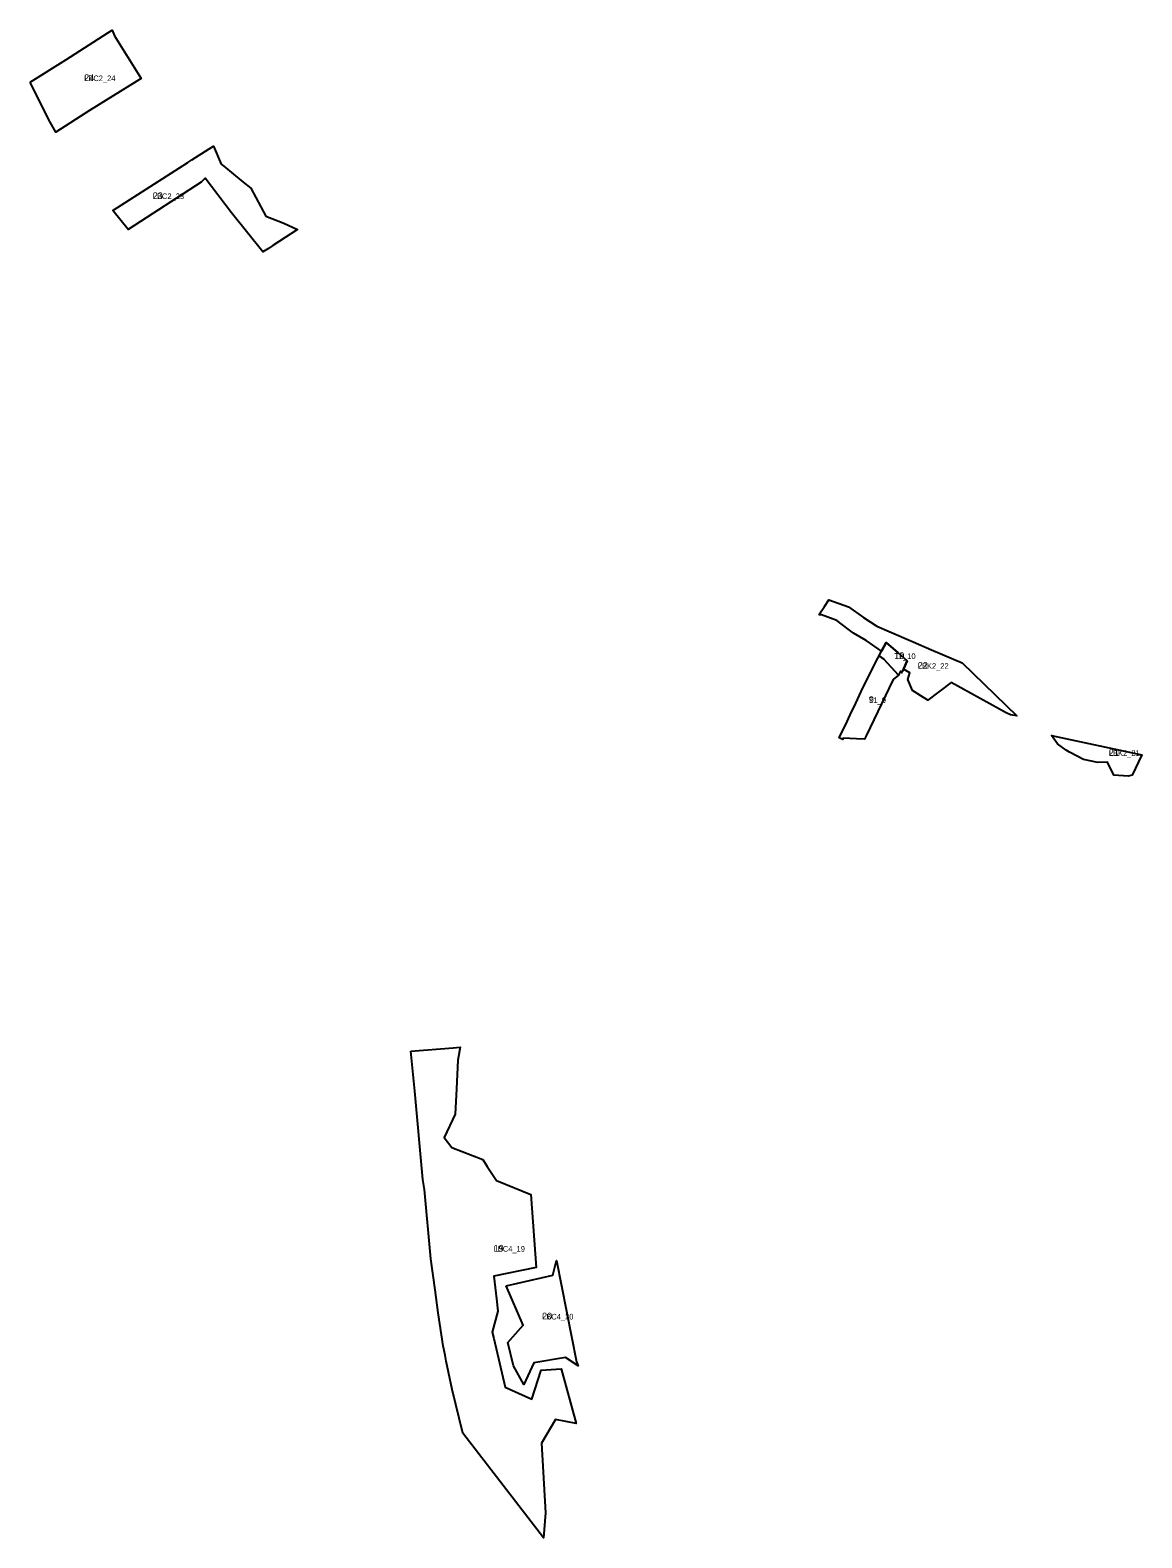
# Model space of a CAD drawing. Extents: x -521969 to -519935, y -1141664 to -1140238.
import ezdxf

# ---------------------------------------------------------------- set-up
doc = ezdxf.new("R2010")
doc.units = 0
for name, color, linetype in [('96120023', 7, 'Continuous'), ('96140023', 7, 'Continuous'), ('ID_VPO', 7, 'Continuous'), ('ID_VPS', 7, 'Continuous')]:
    doc.layers.add(name, color=color, linetype=linetype)

msp = doc.modelspace()

# ---------------------------------------------------------------- linework, layer by layer
at = {"layer": '96120023'}
for points in [[(-520162.5, -1140867.2), (-520152.1, -1140876.1), (-520143.8, -1140883.3), (-520147.2, -1140890.7), (-520148.3, -1140893), (-520148.7, -1140894), (-520149.9, -1140892.7), (-520151.7, -1140896.3), (-520164.6, -1140882), (-520168.9, -1140879), (-520167.8, -1140876.9), (-520166.6, -1140874.8)], [(-520164.6, -1140882), (-520151.7, -1140896.3), (-520156.2, -1140899.9), (-520180.3, -1140950.1), (-520181.8, -1140953.2), (-520189, -1140952.9), (-520200.8, -1140952.2), (-520201.3, -1140953.3), (-520201.3, -1140953.3), (-520204.3, -1140952), (-520197.4, -1140937.4), (-520196.1, -1140934.7), (-520193, -1140928.2), (-520191.2, -1140924.3), (-520184.7, -1140910.7), (-520178.7, -1140898.1), (-520170.1, -1140881.1), (-520168.9, -1140879)]]:
    msp.add_lwpolyline(points, close=True, dxfattribs=at)
at = {"layer": '96140023'}
for points in [[(-520925, -1140368.1), (-520893.1, -1140348.3), (-520855.9, -1140324.2), (-520852.1, -1140321.9), (-520850, -1140327), (-520826.2, -1140365), (-520830.1, -1140367.4), (-520872.1, -1140393.5), (-520902.2, -1140412.7), (-520907.2, -1140403.7), (-520915.8, -1140387), (-520924.4, -1140369.4)], [(-520784.7, -1140439.7), (-520781.1, -1140437.3), (-520765.5, -1140427.6), (-520761.8, -1140425.3), (-520754.8, -1140441.1), (-520752.5, -1140443.1), (-520735.3, -1140457.3), (-520728.4, -1140462.7), (-520724, -1140470.8), (-520715, -1140487.5), (-520699.1, -1140493.8), (-520686.9, -1140499.4), (-520708.8, -1140513.7), (-520712.8, -1140516.2), (-520717.7, -1140519.4), (-520745.7, -1140484.6), (-520769, -1140453.8), (-520772.8, -1140457.3), (-520837.7, -1140499.4), (-520851.5, -1140482.5)], [(-520222.6, -1140842.4), (-520217.5, -1140834.9), (-520213.5, -1140829), (-520196.2, -1140835.4), (-520182.6, -1140844.7), (-520171, -1140852.6), (-520159.9, -1140857.4), (-520138.6, -1140866.5), (-520122.1, -1140873.6), (-520094.9, -1140885.2), (-520046.3, -1140932.3), (-520051.9, -1140931.5), (-520055.7, -1140929.6), (-520059.4, -1140927.6), (-520061.7, -1140926.4), (-520104.6, -1140902.8), (-520125.4, -1140918.4), (-520131.7, -1140914.5), (-520139.1, -1140909.8), (-520143.3, -1140900.1), (-520141.6, -1140894.1), (-520147.2, -1140890.7), (-520143.8, -1140883.3), (-520152.1, -1140876.1), (-520162.5, -1140867.2), (-520166.6, -1140874.8), (-520176.5, -1140867.9), (-520180.3, -1140865.2), (-520191.6, -1140858.7), (-520196.5, -1140855.1), (-520206.4, -1140847.6), (-520220.1, -1140842.5)], [(-519999.3, -1140964.6), (-520002.3, -1140962.9), (-520009.8, -1140957.3), (-520015.2, -1140949.9), (-519934.8, -1140967.1), (-519943.5, -1140985.1), (-519947, -1140986.1), (-519959.9, -1140985.3), (-519965.5, -1140973.7), (-519974.1, -1140974), (-519986.9, -1140971.3)], [(-520585.8, -1141231), (-520548.2, -1141228), (-520541.9, -1141227.5), (-520544.2, -1141238.8), (-520545.4, -1141264.6), (-520546.4, -1141287), (-520556.3, -1141307.7), (-520549.3, -1141316.8), (-520521.9, -1141327.5), (-520517.9, -1141333.5), (-520509.6, -1141346.1), (-520479.1, -1141358.6), (-520474.2, -1141423.4), (-520512.1, -1141431.3), (-520509.7, -1141451.4), (-520508.4, -1141462.4), (-520513.4, -1141481.1), (-520512.1, -1141486.7), (-520502, -1141530.2), (-520478.1, -1141540.6), (-520470, -1141514.9), (-520451.9, -1141513.8), (-520438.6, -1141562.3), (-520457.1, -1141558.7), (-520469.6, -1141579.9), (-520465.9, -1141641.8), (-520467.8, -1141664.2), (-520539.7, -1141570.9), (-520549.2, -1141532.2), (-520554.5, -1141506.8), (-520555.5, -1141501.7), (-520557.2, -1141493.2), (-520561.7, -1141463.9), (-520564.4, -1141443.4), (-520568, -1141415.9), (-520573.9, -1141354), (-520575.3, -1141345.2), (-520582.4, -1141266.6)], [(-520501.1, -1141439.7), (-520459.4, -1141430.3), (-520456.1, -1141417.3), (-520438.5, -1141507.6), (-520436.8, -1141511), (-520448.2, -1141503.5), (-520476.5, -1141508.3), (-520485.3, -1141527.8), (-520494.5, -1141511), (-520499.4, -1141490.3), (-520485.8, -1141475)]]:
    msp.add_lwpolyline(points, close=True, dxfattribs=at)

# ---------------------------------------------------------------- texts
at = {"layer": '96120023'}
for s, p in [('T2_10', (-520155.3, -1140881.8)), ('T1_9', (-520178, -1140921))]:
    msp.add_text(s, height=5, rotation=360, dxfattribs=at).set_placement(p)
at = {"layer": '96140023'}
for s, rotation, p in [('LBC2_24', 0, (-520876.9, -1140367.3)), ('LBC2_23', 0, (-520815.8, -1140472.3)), ('LBK2_22', 360, (-520134.4, -1140890.5)), ('LBK2_21', 0, (-519964.2, -1140968)), ('LBC4_19', 360, (-520512.2, -1141409.4)), ('LBC4_20', 360, (-520469, -1141469.8))]:
    msp.add_text(s, height=5, rotation=rotation, dxfattribs=at).set_placement(p)
at = {"layer": 'ID_VPO'}
for s, rotation, p in [('24', 0, (-520876.9, -1140367.3)), ('23', 0, (-520815.8, -1140472.3)), ('22', 360, (-520134.4, -1140890.5)), ('21', 360, (-519964.2, -1140968)), ('19', 0, (-520512.2, -1141409.4)), ('20', 360, (-520469, -1141469.8))]:
    msp.add_text(s, height=6, rotation=rotation, dxfattribs=at).set_placement(p)
at = {"layer": 'ID_VPS'}
for s, p in [('10', (-520155.3, -1140881.8)), ('9', (-520178, -1140921))]:
    msp.add_text(s, height=6, rotation=0, dxfattribs=at).set_placement(p)

doc.saveas('drawing.dxf')
